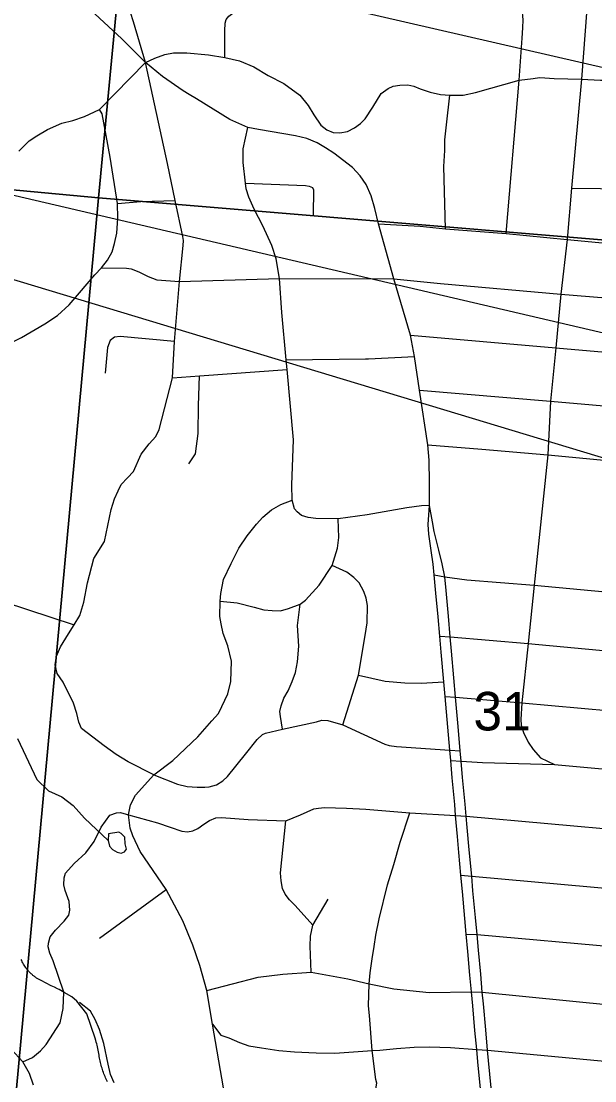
# Model space of a CAD drawing. Extents: x 0 to 34, y 0 to 22.
# Drawn here: x 6.822 to 7.446, y 14.998 to 16.149 of the extents above; entities that cross this region are included whole.
import ezdxf

# ---------------------------------------------------------------- set-up
doc = ezdxf.new("R2010")
doc.units = 0
for name, color, linetype in [('GM_X_City_Street', 7, 'Continuous'), ('GM_X_Corporation', 7, 'Continuous'), ('GM_X_Minor_Lake', 7, 'Continuous'), ('GM_X_Minor_River', 7, 'Continuous'), ('GM_X_Section', 7, 'Continuous'), ('GM_X_Section_Text', 7, 'Continuous'), ('GM_X_State_Route', 7, 'Continuous'), ('SH_Text', 7, 'Continuous')]:
    doc.layers.add(name, color=color, linetype=linetype)

msp = doc.modelspace()

# ---------------------------------------------------------------- linework, layer by layer
at = {"layer": 'GM_X_City_Street'}
for p, q in [((7.1996, 15.7822), (7.2498, 15.7845)), ((6.9077, 15.1526), (6.9801, 15.2055))]:
    msp.add_line(p, q, dxfattribs=at)
for points in [[(6.9576, 16.1039), (6.9446, 16.1481), (6.938, 16.1685), (6.9292, 16.2005), (6.9158, 16.2708), (6.9065, 16.3221), (6.9017, 16.3461), (6.8954, 16.3777), (6.8879, 16.4155), (6.8829, 16.4409), (6.8758, 16.4834)], [(7.3494, 15.9182), (7.3635, 16.0847), (7.3668, 16.1304), (7.3675, 16.1418), (7.3677, 16.1504), (7.3666, 16.1626), (7.3624, 16.181), (7.3606, 16.1864), (7.351, 16.2014)], [(7.0436, 16.1096), (7.0435, 16.1385), (7.0439, 16.1468), (7.0451, 16.1506), (7.048, 16.1544), (7.0523, 16.1576), (7.0618, 16.1597), (7.0941, 16.1631), (7.1051, 16.1627), (7.1206, 16.163), (7.1449, 16.1627), (7.1663, 16.1661), (7.1693, 16.166), (7.1898, 16.164), (7.1946, 16.164), (7.2005, 16.165), (7.2077, 16.1667), (7.2149, 16.1697), (7.2244, 16.1735), (7.2309, 16.1754), (7.236, 16.1767), (7.2551, 16.177)], [(7.4367, 16.1622), (7.431, 16.0858), (7.4203, 15.9676), (7.4154, 15.9117), (7.4087, 15.8525), (7.4032, 15.7941), (7.3975, 15.7359), (7.3945, 15.6777), (7.3795, 15.5361), (7.3733, 15.4726), (7.3663, 15.4083), (7.3653, 15.3902), (7.3654, 15.3841), (7.3681, 15.3759), (7.373, 15.3654), (7.3786, 15.3575), (7.3865, 15.3486), (7.4017, 15.3412)], [(7.431, 16.0858), (7.4518, 16.0847), (7.4583, 16.0849), (7.4655, 16.0857), (7.4882, 16.0929), (7.5403, 16.1096), (7.6042, 16.1126), (7.6322, 16.1136), (7.6571, 16.1178), (7.6658, 16.1199), (7.7119, 16.1318)], [(6.9576, 16.1039), (6.9676, 16.1088), (6.9785, 16.1126), (6.988, 16.1144), (7.0023, 16.1145), (7.0258, 16.1123), (7.0436, 16.1096), (7.0595, 16.1059), (7.0753, 16.0994), (7.0909, 16.0901), (7.1079, 16.0811), (7.1252, 16.0684), (7.1343, 16.0575), (7.1402, 16.0471), (7.1478, 16.0359), (7.1545, 16.0308), (7.1613, 16.0281), (7.1685, 16.0276), (7.1769, 16.0292), (7.1844, 16.0331), (7.1909, 16.0376), (7.196, 16.0429), (7.2046, 16.0556), (7.2135, 16.0703), (7.2211, 16.0757), (7.2266, 16.0783), (7.2339, 16.0796), (7.2424, 16.0799), (7.2491, 16.0783), (7.2558, 16.0754), (7.2667, 16.0719), (7.278, 16.0691), (7.2882, 16.0684), (7.3026, 16.0685), (7.3161, 16.0713), (7.3635, 16.0847), (7.3787, 16.0866), (7.3856, 16.0876), (7.3914, 16.0875), (7.4013, 16.0868), (7.431, 16.0858)], [(6.8201, 16.0077), (6.8312, 16.019), (6.8393, 16.0244), (6.8512, 16.0314), (6.8668, 16.038), (6.8785, 16.0409), (6.8913, 16.0454), (6.9077, 16.0528), (6.9576, 16.1039)], [(6.9666, 15.3302), (6.9387, 15.3443), (6.9258, 15.3523), (6.9127, 15.3617), (6.888, 15.3804), (6.8851, 15.3872), (6.8829, 15.3966), (6.8792, 15.4081), (6.8682, 15.4309), (6.8615, 15.4403), (6.8595, 15.4494), (6.861, 15.459), (6.8652, 15.469), (6.874, 15.4834), (6.8802, 15.4929), (6.8862, 15.5033), (6.8904, 15.5175), (6.8945, 15.5387), (6.9014, 15.565), (6.913, 15.5837), (6.9202, 15.6183), (6.9237, 15.6298), (6.9277, 15.6387), (6.9309, 15.6454), (6.9379, 15.6526), (6.9443, 15.6596), (6.9527, 15.6783), (6.9615, 15.6896), (6.9687, 15.6977), (6.9725, 15.7052), (6.9867, 15.7615), (6.9889, 15.8009), (6.9946, 15.8661), (6.9986, 15.9051), (6.9989, 15.9106), (6.9982, 15.915), (6.9898, 15.9542), (6.9815, 15.9944), (6.9576, 16.1039)], [(7.2834, 15.9232), (7.2817, 15.9909), (7.2825, 16.0083), (7.2828, 16.0201), (7.2844, 16.0364), (7.2882, 16.0684)], [(6.7935, 15.7906), (6.823, 15.8052), (6.8482, 15.82), (6.862, 15.829), (6.8745, 15.8408), (6.8859, 15.8538), (6.9024, 15.8732), (6.9097, 15.8811), (6.9162, 15.8893), (6.9213, 15.8985), (6.9239, 15.9074), (6.9264, 15.9185), (6.9276, 15.9349), (6.9271, 15.951), (6.919, 16.0012), (6.9105, 16.0482), (6.9077, 16.0528)], [(7.2661, 15.6228), (7.2573, 15.6223), (7.2413, 15.6201), (7.1983, 15.6127), (7.1668, 15.6083), (7.1426, 15.6085), (7.1343, 15.6098), (7.1271, 15.6119), (7.1222, 15.6157), (7.1195, 15.6191), (7.1167, 15.6284), (7.1166, 15.6452), (7.1183, 15.6942), (7.1113, 15.7706), (7.1103, 15.7811), (7.1055, 15.8325), (7.103, 15.8692), (7.0993, 15.8909), (7.0946, 15.9051), (7.0851, 15.9266), (7.0756, 15.9448), (7.0696, 15.9577), (7.0669, 15.9668), (7.0662, 15.9729), (7.0637, 15.9953), (7.0637, 16.0102), (7.0687, 16.0336)], [(7.0662, 15.9729), (7.1312, 15.9704), (7.1353, 15.9698), (7.1388, 15.9681), (7.1401, 15.9658), (7.1398, 15.9387)], [(7.4203, 15.9676), (7.4832, 15.9667), (7.5115, 15.9648), (7.548, 15.9587), (7.5751, 15.9551), (7.6023, 15.9569), (7.6372, 15.9564), (7.6501, 15.9557), (7.6734, 15.9508), (7.6905, 15.9472), (7.706, 15.9423), (7.7384, 15.9402)], [(6.9271, 15.951), (6.9526, 15.9531), (6.9898, 15.9542)], [(7.2105, 15.9289), (7.2558, 15.9261), (7.2834, 15.9232), (7.3494, 15.9182), (7.4154, 15.9117), (7.4652, 15.9071), (7.5428, 15.9), (7.6492, 15.8918), (7.7474, 15.8833), (7.7786, 15.8803)], [(6.9097, 15.8811), (6.9367, 15.8807), (6.9419, 15.8798), (6.9504, 15.8766), (6.9604, 15.8716), (6.9699, 15.868), (6.9946, 15.8661), (7.103, 15.8692), (7.2273, 15.8691)], [(7.2273, 15.8691), (7.278, 15.8639), (7.4087, 15.8525), (7.5374, 15.8419), (7.6382, 15.8324), (7.6451, 15.8317), (7.7544, 15.8181)], [(6.9889, 15.8009), (6.93, 15.8064), (6.9237, 15.8056), (6.919, 15.8019), (6.9161, 15.7943), (6.9136, 15.7664)], [(7.2454, 15.8076), (7.4032, 15.7941), (7.532, 15.7829), (7.6468, 15.7734), (7.6655, 15.7716), (7.6798, 15.7702), (7.7165, 15.7644), (7.7659, 15.7546)], [(7.1103, 15.7811), (7.1966, 15.7821), (7.1996, 15.7822)], [(6.9867, 15.7615), (7.0163, 15.7637), (7.1113, 15.7706)], [(7.0047, 15.6681), (7.0117, 15.6789), (7.0147, 15.7009), (7.0152, 15.7313), (7.0163, 15.7637)], [(7.2553, 15.7479), (7.3975, 15.7359), (7.5261, 15.7249), (7.592, 15.7191), (7.6496, 15.7148), (7.7094, 15.7062), (7.7762, 15.6914)], [(7.2643, 15.6886), (7.3227, 15.684), (7.3945, 15.6777), (7.5203, 15.6657), (7.6471, 15.6546), (7.6695, 15.653), (7.68, 15.6519), (7.6923, 15.65), (7.7088, 15.6469), (7.7224, 15.6437), (7.7696, 15.6299), (7.8046, 15.6192)], [(7.0422, 14.9898), (7.0304, 15.0591), (7.024, 15.0956), (7.0166, 15.1228), (7.009, 15.1449), (6.9982, 15.1713), (6.9801, 15.2055), (6.9517, 15.2469), (6.9439, 15.2636), (6.9407, 15.2722), (6.9392, 15.2866), (6.9412, 15.2975), (6.9465, 15.3081), (6.9666, 15.3302), (6.9872, 15.3457), (7.0142, 15.3712), (7.0297, 15.3886), (7.0367, 15.3968), (7.0406, 15.4043), (7.0468, 15.418), (7.0502, 15.4315), (7.0509, 15.4537), (7.0469, 15.4702), (7.042, 15.4838), (7.0397, 15.4942), (7.0381, 15.5022), (7.0385, 15.5188), (7.0395, 15.527), (7.0424, 15.5423), (7.0505, 15.5597), (7.059, 15.5764), (7.0678, 15.5898), (7.078, 15.6023), (7.085, 15.6101), (7.0942, 15.6181), (7.1045, 15.6239), (7.1167, 15.6284)], [(7.0385, 15.5188), (7.0571, 15.5169), (7.0755, 15.5122), (7.0861, 15.5094), (7.095, 15.5085), (7.1041, 15.5084), (7.113, 15.5107), (7.1254, 15.5156), (7.1314, 15.52), (7.146, 15.5361), (7.1601, 15.5576), (7.166, 15.5765), (7.1675, 15.5881), (7.1668, 15.6083)], [(7.1717, 15.3844), (7.1888, 15.4385), (7.1961, 15.4814), (7.1981, 15.4953), (7.1987, 15.5139), (7.1971, 15.5221), (7.1946, 15.5294), (7.1895, 15.5386), (7.1838, 15.5446), (7.1761, 15.5502), (7.1601, 15.5576)], [(7.2712, 15.5474), (7.2825, 15.5451), (7.3065, 15.542), (7.3795, 15.5361), (7.5074, 15.5242), (7.6342, 15.5141), (7.7568, 15.5034), (7.8587, 15.4917)], [(6.7457, 15.5395), (6.804, 15.518), (6.8802, 15.4929)], [(7.1063, 15.3797), (7.1041, 15.3934), (7.1036, 15.3988), (7.1047, 15.4049), (7.1078, 15.4135), (7.1126, 15.4215), (7.1169, 15.4316), (7.1204, 15.4411), (7.1227, 15.4527), (7.1239, 15.4698), (7.1227, 15.4922), (7.1254, 15.5156)], [(7.2772, 15.4809), (7.2884, 15.48), (7.3733, 15.4726), (7.5011, 15.4609), (7.6289, 15.4505), (7.7517, 15.4393), (7.8696, 15.4293), (7.8845, 15.4277), (7.8881, 15.4263), (7.8907, 15.4239), (7.8972, 15.413)], [(7.1888, 15.4385), (7.218, 15.4318), (7.2393, 15.43), (7.2568, 15.4296), (7.2817, 15.431)], [(7.283, 15.4153), (7.2942, 15.4145), (7.3663, 15.4083), (7.4953, 15.3966), (7.6219, 15.3862), (7.7446, 15.3738), (7.8644, 15.3646), (7.8934, 15.3628)], [(6.9666, 15.3302), (6.9923, 15.3198), (7.0026, 15.3175), (7.0136, 15.3165), (7.022, 15.3165), (7.0268, 15.3171), (7.0347, 15.3192), (7.0414, 15.3237), (7.0465, 15.3281), (7.0661, 15.3526), (7.0787, 15.3685), (7.0845, 15.374), (7.0878, 15.3755), (7.1063, 15.3797), (7.1433, 15.3878), (7.1491, 15.3896), (7.1555, 15.3891), (7.1717, 15.3844), (7.2173, 15.3634), (7.2223, 15.362), (7.2302, 15.3609), (7.2882, 15.357), (7.2994, 15.3563)], [(7.289, 15.3458), (7.3005, 15.345), (7.3236, 15.3433), (7.4017, 15.3412), (7.4892, 15.3333), (7.6168, 15.3226), (7.7381, 15.3111), (7.8582, 15.3012)], [(6.8689, 15.0939), (6.8572, 15.1279), (6.8537, 15.1364), (6.8519, 15.1433), (6.852, 15.1471), (6.8541, 15.1539), (6.8596, 15.1613), (6.869, 15.171), (6.8741, 15.1777), (6.8754, 15.183), (6.8745, 15.1925), (6.8703, 15.2044), (6.8689, 15.2104), (6.8693, 15.2181), (6.8707, 15.2233), (6.8802, 15.2338), (6.8928, 15.2453), (6.9017, 15.2577), (6.9094, 15.2733), (6.9186, 15.2863), (6.9259, 15.2889), (6.9303, 15.2891), (6.9392, 15.2866), (6.9707, 15.278), (6.9843, 15.2732), (6.9968, 15.269), (7.003, 15.2682), (7.009, 15.2691), (7.0142, 15.2719), (7.0209, 15.2763), (7.0269, 15.2806), (7.0338, 15.2834), (7.0401, 15.2837), (7.0692, 15.2814), (7.11, 15.2799), (7.1259, 15.2867), (7.1403, 15.293), (7.1453, 15.2939), (7.1519, 15.2945), (7.1759, 15.294), (7.1969, 15.2929), (7.2445, 15.2888), (7.2944, 15.2858), (7.3058, 15.2851)], [(7.1393, 15.1666), (7.12, 15.1879), (7.114, 15.1941), (7.1091, 15.2003), (7.1063, 15.2067), (7.1048, 15.2147), (7.1042, 15.2237), (7.11, 15.2799)], [(7.1956, 14.9229), (7.1968, 14.9412), (7.2053, 14.9744), (7.2089, 14.9951), (7.2076, 14.999), (7.2037, 15.0304), (7.2009, 15.0685), (7.1996, 15.0791), (7.2006, 15.1031), (7.2015, 15.1148), (7.2037, 15.1302), (7.206, 15.1435), (7.2078, 15.1558), (7.2114, 15.1737), (7.2204, 15.2104), (7.2274, 15.2327), (7.2343, 15.2569), (7.2445, 15.2888)], [(7.3058, 15.2851), (7.4831, 15.2692), (7.6104, 15.2579), (7.7327, 15.247), (7.8548, 15.2369), (7.8836, 15.2341)], [(7.3, 15.2209), (7.3118, 15.2199), (7.4771, 15.2051), (7.6037, 15.1942), (7.7267, 15.1831), (7.8504, 15.1718), (7.8788, 15.1698)], [(7.1376, 15.1155), (7.1365, 15.1438), (7.1366, 15.1547), (7.1393, 15.1666), (7.1559, 15.1949)], [(7.3058, 15.1569), (7.3178, 15.1567), (7.4716, 15.1428), (7.598, 15.1316), (7.7211, 15.1205), (7.8454, 15.1097), (7.874, 15.1075)], [(7.024, 15.0956), (7.0799, 15.1103), (7.1065, 15.1135), (7.1376, 15.1155), (7.1774, 15.1083), (7.2006, 15.1031), (7.2271, 15.0974), (7.2658, 15.0937), (7.3117, 15.0943), (7.3232, 15.0938)], [(6.8242, 15.0182), (6.8346, 15.0231), (6.8435, 15.0301), (6.8495, 15.0371), (6.8649, 15.0607), (6.8682, 15.076), (6.8689, 15.0939)], [(6.9236, 14.9953), (6.9196, 15.0045), (6.9169, 15.0156), (6.9122, 15.0382), (6.9076, 15.0532), (6.903, 15.0643), (6.8979, 15.0732), (6.8858, 15.0826)], [(7.3232, 15.0938), (7.4656, 15.0799), (7.5924, 15.0693), (7.6718, 15.0615), (7.7153, 15.0578), (7.8412, 15.0477), (7.8694, 15.0456)], [(7.0304, 15.0591), (7.0393, 15.0473), (7.0479, 15.0443), (7.0596, 15.0391), (7.0696, 15.0356), (7.0835, 15.0334), (7.1022, 15.0304), (7.1195, 15.029), (7.1429, 15.0281), (7.1633, 15.0277), (7.2037, 15.0304), (7.2121, 15.031), (7.2302, 15.0326), (7.2494, 15.034), (7.2656, 15.0344), (7.2889, 15.0337), (7.3173, 15.0317), (7.3291, 15.0309)], [(6.8358, 14.9928), (6.8315, 15.0054), (6.8242, 15.0182), (6.8115, 15.0321)], [(7.3291, 15.0309), (7.4601, 15.0185), (7.5868, 15.007), (7.7096, 14.9952), (7.8374, 14.9853), (7.8686, 14.9827)]]:
    msp.add_lwpolyline(points, dxfattribs=at)
at = {"layer": 'GM_X_Corporation'}
msp.add_lwpolyline([(6.9163, 14.9966), (6.9156, 14.998), (6.9149, 14.9995), (6.9142, 15.0009), (6.9136, 15.0024), (6.913, 15.0039), (6.9124, 15.0053), (6.9118, 15.0068), (6.9113, 15.0084), (6.9107, 15.0099), (6.9103, 15.0114), (6.9098, 15.0129), (6.9094, 15.0145), (6.909, 15.016), (6.9086, 15.0176), (6.9082, 15.0192), (6.9079, 15.0207), (6.9076, 15.0223), (6.9073, 15.0239), (6.9071, 15.0255), (6.9068, 15.0273), (6.9065, 15.0291), (6.9062, 15.0308), (6.9058, 15.0326), (6.9054, 15.0344), (6.905, 15.0362), (6.9045, 15.0379), (6.904, 15.0397), (6.9035, 15.0414), (6.9027, 15.0439), (6.8938, 15.0703), (6.8831, 15.0843), (6.8774, 15.0888), (6.8692, 15.0937), (6.8637, 15.0967), (6.862, 15.0975), (6.8585, 15.0992), (6.8551, 15.1008), (6.8441, 15.1066), (6.8428, 15.1073), (6.842, 15.1077), (6.8413, 15.1081), (6.8406, 15.1085), (6.8399, 15.1089), (6.8392, 15.1093), (6.8385, 15.1098), (6.8379, 15.1102), (6.8372, 15.1107), (6.8365, 15.1112), (6.8359, 15.1117), (6.8352, 15.1122), (6.8346, 15.1127), (6.834, 15.1133), (6.8334, 15.1138), (6.8328, 15.1143), (6.8327, 15.1144), (6.8322, 15.1149), (6.8316, 15.1155), (6.831, 15.1161), (6.8304, 15.1167), (6.8299, 15.1173), (6.8294, 15.1179), (6.8288, 15.1185), (6.8279, 15.1198), (6.8272, 15.1209), (6.8264, 15.1221), (6.8257, 15.1233), (6.825, 15.1245), (6.8243, 15.1257), (6.8237, 15.1269), (6.8231, 15.1282), (6.8224, 15.1294)], dxfattribs=at)
at = {"layer": 'GM_X_Minor_Lake'}
for points in [[(6.9356, 15.255), (6.9349, 15.2623), (6.9312, 15.2662), (6.9286, 15.2677), (6.9172, 15.2661)], [(6.9172, 15.2661), (6.917, 15.2588), (6.9184, 15.2527), (6.9218, 15.2489), (6.9267, 15.2461), (6.9312, 15.2449), (6.9346, 15.2463), (6.937, 15.2493), (6.9356, 15.255)]]:
    msp.add_lwpolyline(points, dxfattribs=at)
at = {"layer": 'GM_X_Minor_River'}
msp.add_lwpolyline([(6.8186, 15.3697), (6.8396, 15.3251), (6.8522, 15.3126), (6.8665, 15.3062), (6.8788, 15.2967), (6.8914, 15.2831), (6.917, 15.2588)], dxfattribs=at)
at = {"layer": 'GM_X_Section'}
for points in [[(6.2217, 17.0542), (7.0031, 16.9763), (6.9063, 15.9571), (5.9113, 16.0496), (5.9234, 16.1293), (5.9728, 16.1367), (6.0607, 16.16), (6.1382, 16.2162), (6.2051, 16.2691), (6.2419, 16.3134), (6.2637, 16.3615), (6.2822, 16.4596), (6.2827, 16.5907), (6.2524, 16.8893)], [(7.0031, 16.9763), (8.0016, 16.8868), (7.9035, 15.8736), (6.9063, 15.9571)], [(5.9113, 16.0496), (6.9063, 15.9571), (6.8145, 14.9579), (6.796, 14.9605), (5.8372, 15.0451), (5.8133, 15.0467)], [(6.9063, 15.9571), (7.9035, 15.8736), (7.8278, 14.865), (6.8145, 14.9579)]]:
    msp.add_lwpolyline(points, close=True, dxfattribs=at)
at = {"layer": 'GM_X_State_Route'}
for points in [[(6.9576, 16.1039), (6.9318, 16.1297), (6.893, 16.1658), (6.8424, 16.2163), (6.7989, 16.2691), (6.7768, 16.3031)], [(7.0051, 16.0691), (6.9984, 16.0732), (6.9759, 16.0889), (6.9576, 16.1039)], [(7.2105, 15.9289), (7.2065, 15.9454), (7.2028, 15.959), (7.1972, 15.9714), (7.1907, 15.981), (7.1823, 15.9901), (7.162, 16.0054), (7.1532, 16.0114), (7.144, 16.0166), (7.1326, 16.0215), (7.1204, 16.0245), (7.0801, 16.0311), (7.0687, 16.0336), (7.0492, 16.042), (7.0128, 16.0645), (7.0051, 16.0691)], [(7.276, 15.5741), (7.2709, 15.5944), (7.2691, 15.605), (7.2661, 15.6228), (7.2661, 15.6478), (7.2657, 15.672), (7.2643, 15.6886), (7.2553, 15.7479), (7.2498, 15.7845), (7.2454, 15.8076), (7.2273, 15.8691), (7.2105, 15.9289)], [(7.3212, 14.9887), (7.3185, 15.0183), (7.3173, 15.0317), (7.3153, 15.0521), (7.3129, 15.0792), (7.3117, 15.0943), (7.3099, 15.1125), (7.3076, 15.1382), (7.3058, 15.1569), (7.3045, 15.1739), (7.3017, 15.2034), (7.3, 15.2209), (7.2978, 15.2456), (7.2964, 15.2632), (7.2944, 15.2858), (7.2934, 15.2977), (7.2905, 15.3267), (7.289, 15.3458), (7.2882, 15.357), (7.2859, 15.382), (7.283, 15.4153), (7.2817, 15.431), (7.2786, 15.4634), (7.2772, 15.4809), (7.2753, 15.5018), (7.273, 15.5274), (7.2712, 15.5474), (7.2699, 15.5588), (7.2678, 15.5738), (7.2651, 15.5916), (7.2644, 15.6021), (7.2661, 15.6228)], [(7.3329, 14.9898), (7.3301, 15.0195), (7.3291, 15.0309), (7.3271, 15.053), (7.3245, 15.0814), (7.3232, 15.0938), (7.3216, 15.1133), (7.3191, 15.1397), (7.3178, 15.1567), (7.3159, 15.1752), (7.3131, 15.204), (7.3118, 15.2199), (7.3091, 15.2486), (7.3069, 15.2728), (7.3058, 15.2851), (7.3046, 15.2981), (7.3019, 15.3273), (7.3005, 15.345), (7.2994, 15.3563), (7.297, 15.3825), (7.2942, 15.4145), (7.2924, 15.4356), (7.2899, 15.4644), (7.2884, 15.48), (7.2865, 15.5023), (7.2842, 15.5304), (7.2825, 15.5451), (7.2797, 15.5594), (7.276, 15.5741)]]:
    msp.add_lwpolyline(points, dxfattribs=at)
at = {"layer": 'SH_Text'}
for points in [[(5.5598, 16.5345), (9.346, 15.9306), (10.7296, 15.939), (10.7249, 15.654), (9.3684, 15.6583)], [(5.4805, 16.2716), (9.333, 15.3718), (10.6987, 15.3733), (10.6963, 15.0992), (9.3554, 15.0994)]]:
    msp.add_lwpolyline(points, close=True, dxfattribs=at)

# ---------------------------------------------------------------- texts
at = {"layer": 'GM_X_Section_Text'}
msp.add_text('31', height=0.04186, rotation=0, dxfattribs=at).set_placement((7.3137, 15.3783))

doc.saveas('drawing.dxf')
